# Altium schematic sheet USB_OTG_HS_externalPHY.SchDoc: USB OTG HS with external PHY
size A4; Date: Not used; ApprovedBy: Not used; CheckedBy: Not used; Author: Not used; CompanyName: STMicroelectronics; DrawnBy: Not used; Engineer: Not used; Organization: Not used; Address1: Not used; Address2: Not used; Address3: Not used; Address4: Not used; DocumentNumber: Not used; Revision: Not used; SheetNumber: 6; SheetTotal: 23
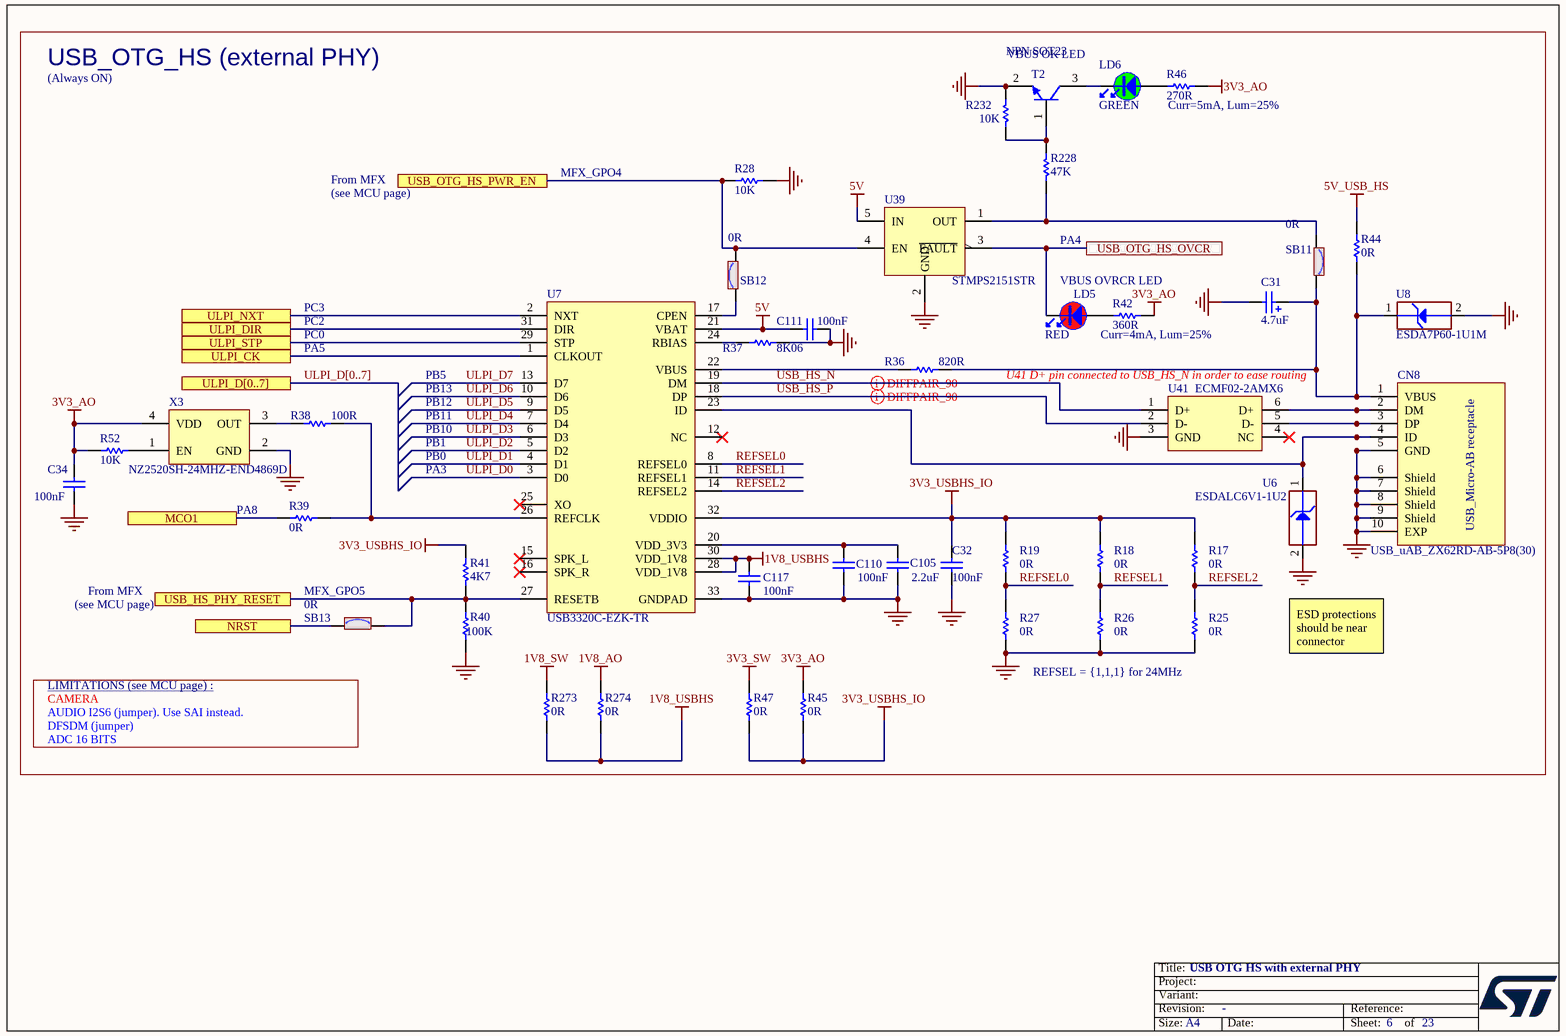
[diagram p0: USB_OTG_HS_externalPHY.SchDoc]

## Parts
C31  value 4.7uF  [CPOL_TAJ-A_1206_H180]  (hidden comment: Cap_POL_TANA)
C32  value 100nF  [C0402]  (hidden comment: Capacitor)
C34  value 100nF  [C0402]  (hidden comment: Capacitor)
C105  value 2.2uF  [C0603]  (hidden comment: Capacitor)
C110  value 100nF  [C0402]  (hidden comment: Capacitor)
C111  value 100nF  [C0402]  (hidden comment: Capacitor)
C117  value 100nF  [C0402]  (hidden comment: Capacitor)
CN8  value USB_uAB_ZX62RD-AB-5P8(30)  [CON_USBMICROAB_MOLEX_47590-0001_H3]  (hidden comment: USB_uAB_47590.0001)
LD5  value RED  [LED_0603_VISHAY_VLMS1300-GS08_RED_1A2K_H0P8]  (hidden comment: LED_red)
LD6  value GREEN  [LED_0603_OSRAM_LG-Q396-PS-35_GREEN_1A2K_H0P4]  (hidden comment: LED_green)
R17  value 0R  [R0603]  (hidden comment: Resistor)
R18  value 0R  [R0603]  (hidden comment: Resistor)
R19  value 0R  [R0603]  (hidden comment: Resistor)
R25  value 0R  [R0603]  (hidden comment: Resistor)
R26  value 0R  [R0603]  (hidden comment: Resistor)
R27  value 0R  [R0603]  (hidden comment: Resistor)
R28  value 10K  [R0402]  (hidden comment: Resistor)
R36  value 820R  [R0603]  (hidden comment: Resistor)
R37  value 8K06  [R0603]  (hidden comment: Resistor)
R38  value 100R  [R0402]  (hidden comment: Resistor)
R39  value 0R  [R0402]  (hidden comment: Resistor)
R40  value 100K  [R0402]  (hidden comment: Resistor)
R41  value 4K7  [R0402]  (hidden comment: Resistor)
R42  value 360R  [R0402]  (hidden comment: Resistor)
R44  value 0R  [R0805]  (hidden comment: Resistor)
R45  value 0R  [R0603]  (hidden comment: Resistor)
R46  value 270R  [R0402]  (hidden comment: Resistor)
R47  value 0R  [R0603]  (hidden comment: Resistor)
R52  value 10K  [R0402]  (hidden comment: Resistor)
R228  value 47K  [R0402]  (hidden comment: Resistor)
R232  value 10K  [R0402]  (hidden comment: Resistor)
R273  value 0R  [R0603]  (hidden comment: Resistor)
R274  value 0R  [R0603]  (hidden comment: Resistor)
SB11  value 0R  [SOLDER-BRIDGE_R0603-0R]  (hidden comment: SB_ON)
SB12  value 0R  [SOLDER-BRIDGE_R0603-0R]  (hidden comment: SB_ON)
SB13  value 0R  [SOLDER-BRIDGE_R0603-0R]  (hidden comment: SB_ON)
T2  value NPN SOT23  [NPN_SOT23]  (hidden comment: 9013-SOT23)
U6  value ESDALC6V1-1U2  [ESD_ST0201]  (hidden comment: ESD-TRANSIL)
U7  value USB3320C-EZK-TR  [ICC_QFN32-EPAD_5X5_P050]  (hidden comment: USB3320C-EZK)
U8  value ESDA7P60-1U1M  [ESD_QFN2_1P6X1_P125]  (hidden comment: ESD-TRANSIL)
U39  STMPS2151STR  [MOS_SOT23-5L]
U41  ECMF02-2AMX6  [ESD_QFN-6L_1P7X1P5_P050]
X3  Manufacturer_Part_Number: NZ2520SH-24MHZ-END4869D  [OSC_NDK_NZ2520SB_4P]  (hidden comment: OSCILLATOR_4_PINS)

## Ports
MCO1, NRST, ULPI_CK, ULPI_D[0..7], ULPI_DIR, ULPI_NXT, ULPI_STP, USB_HS_PHY_RESET, USB_OTG_HS_OVCR, USB_OTG_HS_PWR_EN

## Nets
1V8_AO: R274.1
1V8_SW: R273.1
1V8_USBHS: C117.1 R273.2 R274.2 U7.28(VDD_1V8) U7.30(VDD_1V8)
3V3_AO: C34.2 R42.2 R45.1 R46.2 R52.1 X3.4(VDD)
3V3_SW: R47.1
3V3_USBHS_IO: C32.2 R17.2 R18.2 R19.2 R41.2 R45.2 R47.2 U7.32(VDDIO)
5V: C111.1 U7.21(VBAT) U39.5(IN)
5V_USB_HS: R44.2
GND: C31.2 C32.1 C34.1 C105.1 C110.2 C111.2 C117.2 CN8.5(GND) CN8.6(Shield) CN8.7(Shield) CN8.8(Shield) CN8.9(Shield) CN8.10(EXP) R25.1 R26.1 R27.1 R28.2 R37.2 R40.1 R232.1 T2.2(E) U6.2(GND) U7.33(GNDPAD) U8.2(GND) U39.2(GND) U41.3(GND) X3.2(GND)
MCO1: R39.1 ; port MCO1
NRST: SB13.2 ; port NRST
REFSEL0: R19.1 R27.2 U7.8(REFSEL0)
REFSEL1: R18.1 R26.2 U7.11(REFSEL1)
REFSEL2: R17.1 R25.2 U7.14(REFSEL2)
ULPI_CK: U7.1(CLKOUT) ; port ULPI_CK
ULPI_D0: U7.3(D0)
ULPI_D1: U7.4(D1)
ULPI_D2: U7.5(D2)
ULPI_D3: U7.6(D3)
ULPI_D4: U7.7(D4)
ULPI_D5: U7.9(D5)
ULPI_D6: U7.10(D6)
ULPI_D7: U7.13(D7)
ULPI_DIR: U7.31(DIR) ; port ULPI_DIR
ULPI_NXT: U7.2(NXT) ; port ULPI_NXT
ULPI_STP: U7.29(STP) ; port ULPI_STP
USB_HS_N: U7.19(DM) U41.1(D+)
USB_HS_P: U7.18(DP) U41.2(D-)
USB_HS_PHY_RESET: R40.2 R41.1 SB13.1 U7.27(RESETB) ; port USB_HS_PHY_RESET
USB_OTG_HS_OVCR: LD5.2 U39.3(~{FAULT}) ; port USB_OTG_HS_OVCR
USB_OTG_HS_PWR_EN: R28.1 SB12.1 U39.4(EN) ; port USB_OTG_HS_PWR_EN
NetC31_1: C31.1 CN8.1(VBUS) R36.2 R44.1 SB11.2 U8.1(IO1)
NetC105_2: C105.2 C110.1 U7.20(VDD_3V3)
NetCN8_2: CN8.2(DM) U41.6(D+)
NetCN8_3: CN8.3(DP) U41.5(D-)
NetCN8_4: CN8.4(ID) U6.1(IO1) U7.23(ID)
NetLD5_1: LD5.1 R42.1
NetLD6_1: LD6.1 R46.1
NetLD6_2: LD6.2 T2.3(C)
NetR36_1: R36.1 U7.22(VBUS)
NetR37_1: R37.1 U7.24(RBIAS)
NetR38_1: R38.1 X3.3(OUT)
NetR38_2: R38.2 R39.2 U7.26(REFCLK)
NetR52_2: R52.2 X3.1(EN)
NetR228_1: R228.1 SB11.1 U39.1(OUT)
NetR228_2: R228.2 R232.2 T2.1(B)
NetSB12_2: SB12.2 U7.17(CPEN)

Not connected (* = marked no-connect by the designer): U7 12(NC)* 15(SPK_L)* 16(SPK_R)* 25(XO)*; U41 4(NC)*

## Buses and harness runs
bus ULPI_D[0..7] = port ULPI_D[0..7]

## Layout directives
differential pair: USB_HS_N, USB_HS_P

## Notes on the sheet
- VBUS OK LED
- USB_OTG_HS (external PHY)
- (Always ON)
- (near R46) Curr=5mA, Lum=25%
- MFX_GPO4
- From MFX
- (see MCU page)
- PA4
- PC3
- VBUS OVRCR LED
- PC2
- PC0
- PA5
- PB5
- (near U41) U41 D+ pin connected to USB_HS_N in order to ease routing
- Curr=4mA, Lum=25%
- PB1
- PB10
- PB11
- PB12
- PB13
- PA8
- PA3
- PB0
- (near SB13) MFX_GPO5
- ESD protections should be near connector
- LIMITATIONS (see MCU page) :
- AUDIO I2S6 (jumper). Use SAI instead.
- CAMERA
- REFSEL = {1,1,1} for 24MHz
- DFSDM (jumper)
- ADC 16 BITS

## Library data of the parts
C31 = MCD-00007: Capacitor, Tantalum, 4.7uF, 16V, 10%, 4ohms, pkg Type_A (3216 metric), T=1.6mm; Manufacturer_Part_Number: TAJA475K016R; Manufacturer: AVX; Part_Preference: Recommended; Partial_Alternate_Internal_Part_Number: MCD-03149; Provided_By: SUBCO; ECCN_US: EAR99; ECCN_EU: NEC; Component_Country_Of_Origin: El Salvador; ID: 2473; Order_Code_RS: 197269; ShowFields: YES
C32 C34 C110 C111 C117 = MCD-00006: Capacitor, MLCC, 100nF, 16V, X7R, 10%, 0402, T=0.5mm; Manufacturer_Part_Number: CC0402KRX7R7BB104; Manufacturer: YAGEO; Alternate_Manufacturer_Part_Number: GCM155R71C104KA55D; Alternate_Manufacturer: MURATA; Part_Preference: Recommended; Partial_Alternate_Internal_Part_Number: MCD-03299; Provided_By: SUBCO; ECCN_US: EAR99; ECCN_EU: NEC; Component_Country_Of_Origin: China; ID: 2474; Order_Code_RS: 9402047; ShowFields: YES
C105 = MCD-00012: Capacitor, MLCC, 2.2uF, 10V, X5R, 10%, 0603, T=0,8mm; Manufacturer_Part_Number: CC0603KRX5R6BB225; Manufacturer: YAGEO; Alternate_Manufacturer_Part_Number: C0603C225K8PACTU; Alternate_Manufacturer: KEMET; BMS_Part_Number: 9142010; Part_Preference: Recommended; Partial_Alternate_Internal_Part_Number: MCD-00551; Provided_By: SUBCO; ECCN_US: EAR99; ECCN_EU: NEC; Component_Country_Of_Origin: China; ID: 2467; Order_Code_RS: 2370679; ShowFields: YES
CN8 = MCD-00661: USB-MICRO-AB Receptacle, RA, SMT + DIP, Standard, Top Mount, USB certified (symbol & footprint compatible with MCD-00022); Part_Type: Connector; Manufacturer_Part_Number: ZX62RD-AB-5P8(30); Manufacturer: HIROSE; Part_Preference: Recommended; Provided_By: SUBCO; Component_Country_Of_Origin: Japan; ID: 3083; Order_Code_RS: 136-1404; ShowFields: YES
LD5 = MCD-00587: LED Red, 0603 SMD, 2V Forward Voltage; Part_Type: Display; Manufacturer_Part_Number: VLMS1300-GS08; Manufacturer: VISHAY; Alternate_Manufacturer_Part_Number: LS Q976-NR-1; Alternate_Manufacturer: OSRAM OPTO SEMICONDUCTORS; Full_Alternate_Internal_Part_Number: MCD-02401; Part_Preference: Recommended; Provided_By: SUBCO; Component_Country_Of_Origin: China; ID: 3154; ShowFields: YES
LD6 = MCD-00588: LED Green, 0603 SMD, Forward Voltage Typ=2V, Max=2.5V; Part_Type: Display; Manufacturer_Part_Number: LG Q396-PS-35; Manufacturer: OSRAM OPTO SEMICONDUCTORS; Alternate_Manufacturer_Part_Number: VLMTG1300-GS08; Alternate_Manufacturer: VISHAY SEMICONDUCTOR OPTO DIVISION; Part_Preference: Recommended; Partial_Alternate_Internal_Part_Number: MCD-02400, MCD-03155; Provided_By: SUBCO; Component_Country_Of_Origin: Unknown; ID: 3155; ShowFields: YES
R17-R19 R25-R27 R45 R47 R273 R274 = MCD-00056: Resistor,0R,0603,5%,1/10W; Manufacturer_Part_Number: RC0603JR-070RL; Manufacturer: YAGEO; Part_Preference: Recommended; Provided_By: SUBCO; ECCN_US: EAR99; ECCN_EU: NEC; Component_Country_Of_Origin: China; ID: 2536; Order_Code_RS: 9233130RL; ShowFields: YES
R28 R52 R232 = MCD-00053: Resistor,10K,0402,1%,1/16W; Manufacturer_Part_Number: RC0402FR-0710KL; Manufacturer: YAGEO; BMS_Part_Number: 9131590; Part_Preference: Recommended; Provided_By: SUBCO; ECCN_US: EAR99; ECCN_EU: NEC; Component_Country_Of_Origin: China; ID: 2539; Order_Code_RS: 9239359; ShowFields: YES
R36 = MCD-00528: Resistor,820R,0603,1%,1/10W; Manufacturer_Part_Number: RC0603FR-07820RL; Manufacturer: YAGEO; BMS_Part_Number: 9129759; Part_Preference: Recommended; Provided_By: SUBCO; ECCN_US: EAR99; ECCN_EU: NEC; Component_Country_Of_Origin: China; ID: 3218; ShowFields: YES
R37 = MCD-00570: Resistor,8K06,0603,1%,1/10W; Manufacturer_Part_Number: RC0603FR-078K06L; Manufacturer: YAGEO; Part_Preference: Recommended; Provided_By: SUBCO; ECCN_US: EAR99; ECCN_EU: NEC; Component_Country_Of_Origin: China; ID: 3177; ShowFields: YES
R38 = MCD-00067: Resistor,100R,0402,1%,1/16W; Manufacturer_Part_Number: RC0402FR-07100RL; Manufacturer: YAGEO; Part_Preference: Recommended; Provided_By: SUBCO; ECCN_US: EAR99; ECCN_EU: NEC; Component_Country_Of_Origin: China; ID: 2527; Order_Code_RS: 9239111; ShowFields: YES
R39 = MCD-00052: Resistor,0R,0402,5%,1/16W; Manufacturer_Part_Number: RC0402JR-070RL; Manufacturer: YAGEO; Part_Preference: Recommended; Provided_By: SUBCO; ECCN_US: EAR99; ECCN_EU: NEC; Component_Country_Of_Origin: China; ID: 2540; Order_Code_RS: 9232516RL; ShowFields: YES
R40 = MCD-00059: Resistor,100K,0402,1%,1/16W; Manufacturer_Part_Number: RC0402FR-07100KL; Manufacturer: YAGEO; Alternate_Manufacturer_Part_Number: RT0402FRE07100KL; Part_Preference: Recommended; Partial_Alternate_Internal_Part_Number: MCD-03301; Provided_By: SUBCO; ECCN_US: EAR99; ECCN_EU: NEC; Component_Country_Of_Origin: China; ID: 2533; Order_Code_RS: 2421891; ShowFields: YES
R41 = MCD-00065: Resistor,4K7,0402,1%,1/16W; Manufacturer_Part_Number: RC0402FR-074K7L; Manufacturer: YAGEO; Alternate_Manufacturer_Part_Number: RT0402FRE074K7L; Part_Preference: Recommended; Partial_Alternate_Internal_Part_Number: MCD-03300; Provided_By: SUBCO; ECCN_US: EAR99; ECCN_EU: NEC; Component_Country_Of_Origin: China; ID: 2526; Order_Code_RS: 9239316; ShowFields: YES
R42 = MCD-00461: Resistor,360R,0402,1%,1/16W; Manufacturer_Part_Number: RC0402FR-07360RL; Manufacturer: YAGEO; Part_Preference: Recommended; Provided_By: SUBCO; ECCN_US: EAR99; ECCN_EU: NEC; Component_Country_Of_Origin: China; ID: 2816; ShowFields: YES
R44 = MCD-00179: Resistor,0R,0805,5%; Manufacturer_Part_Number: RC0805JR-070RL; Manufacturer: YAGEO; Part_Preference: Recommended; Provided_By: SUBCO; ECCN_US: EAR99; ECCN_EU: NEC; Component_Country_Of_Origin: China; ID: 2685; ShowFields: YES
R46 = MCD-00441: Resistor,270R,0402,1%,1/16W; Manufacturer_Part_Number: RC0402FR-07270RL; Manufacturer: YAGEO; Part_Preference: Recommended; Provided_By: SUBCO; ECCN_US: EAR99; ECCN_EU: NEC; Component_Country_Of_Origin: China; ID: 2838; ShowFields: YES
R228 = MCD-00063: Resistor,47K,0402,1%,1/16W; Manufacturer_Part_Number: RC0402FR-0747KL; Manufacturer: YAGEO; Part_Preference: Recommended; Provided_By: SUBCO; ECCN_US: EAR99; ECCN_EU: NEC; Component_Country_Of_Origin: China; ID: 2528; Order_Code_RS: 9239430; ShowFields: YES
SB11-SB13 = MCD-00071: Solder Bridge ON; Part_Type: Resistor; Manufacturer_Part_Number: RC0603JR-070RL; Manufacturer: YAGEO; Manufacturer_HQ_COO: Unknown; Part_Preference: Recommended; Provided_By: SUBCO; Component_Country_Of_Origin: China; ID: 2521; Order_Code_RS: 199-5647; ShowFields: YES
T2 = MCD-00073: NPN Bipolar Transistor; Manufacturer_Part_Number: BSR14; Manufacturer: ON SEMICONDUCTOR; Part_Type: IC; Alternate_Manufacturer_Part_Number: MMBT2222LT1G / MMBT2222ALT1G / MMBT2222ALT3G; Part_Preference: Recommended; Partial_Alternate_Internal_Part_Number: MCD-01737, MCD-03305, , MCD-02988; Provided_By: SUBCO; ECCN_US: EAR99; ECCN_EU: NEC; Component_Country_Of_Origin: Unknown; ID: 2519; ShowFields: YES
U6 = MCD-00170: ESD protection 6V1; Part_Type: Diode; Manufacturer: STMICROELECTRONICS; BMS_Part_Number: 9151132; Manufacturer_HQ_COO: EU; Part_Preference: Recommended; Provided_By: SUBCO with ST control; ECCN_US: EAR99; ECCN_EU: NEC; Component_Country_Of_Origin: China; ID: 2696; Order_Code_RS: 795-8404; ShowFields: YES
U7 = MCD-00569: USB3320C,  Hi-Speed USB Host, Device or OTG PHY with ULPI Low Pin Interface; Manufacturer: MICROCHIP; Part_Type: IC; Part_Preference: Recommended; Provided_By: SUBCO; ECCN_US: EAR99; ECCN_EU: NEC; Component_Country_Of_Origin: Unknown; ID: 3179; Order_Code_RS: 889-5840; ShowFields: YES
U8 = MCD-00251: High power transient voltage suppressor, 7V breakdown; Part_Type: Diode; Manufacturer: STMICROELECTRONICS; BMS_Part_Number: 9179042; Manufacturer_HQ_COO: EU; Part_Preference: Recommended; Provided_By: SUBCO with ST control; ECCN_US: EAR99; ECCN_EU: NEC; Component_Country_Of_Origin: China; ID: 2618; Order_Code_RS: 110-6381; ShowFields: YES
U39 = MCD-00159: 500mA, Enhanced single channel power switches with active high enable pin; Manufacturer: STMICROELECTRONICS; Part_Type: IC; Alternate_Manufacturer_Part_Number: TPS2051C; Alternate_Manufacturer: TEXAS INSTRUMENTS; BMS_Part_Number: 9159009; Part_Preference: Recommended; Provided_By: SUBCO with ST control; ECCN_US: EAR99; ECCN_EU: NEC; Component_Country_Of_Origin: Malaysia; ID: 2708; Order_Code_RS: 165-5516; ShowFields: YES
U41 = MCD-00649: Common mode filter with ESD protection for USB 2.0 interface; Part_Type: Diode; Manufacturer: STMICROELECTRONICS; BMS_Part_Number: 9151138; Manufacturer_HQ_COO: EU; Part_Preference: Recommended; Provided_By: SUBCO with ST control; ECCN_US: EAR99; ECCN_EU: NEC; Component_Country_Of_Origin: China; ID: 3094; Order_Code_RS: 880-5276; ShowFields: YES
X3 = MCD-01976: Oscillator, SPXO, 24MHz, +/-50ppm, square wave, 3V3, 2.5x2mm; Part_Type: Crystal_Osc; Manufacturer: NDK; Part_Preference: Recommended; Component_Country_Of_Origin: Unknown; ShowFields: YES; ID: 4076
